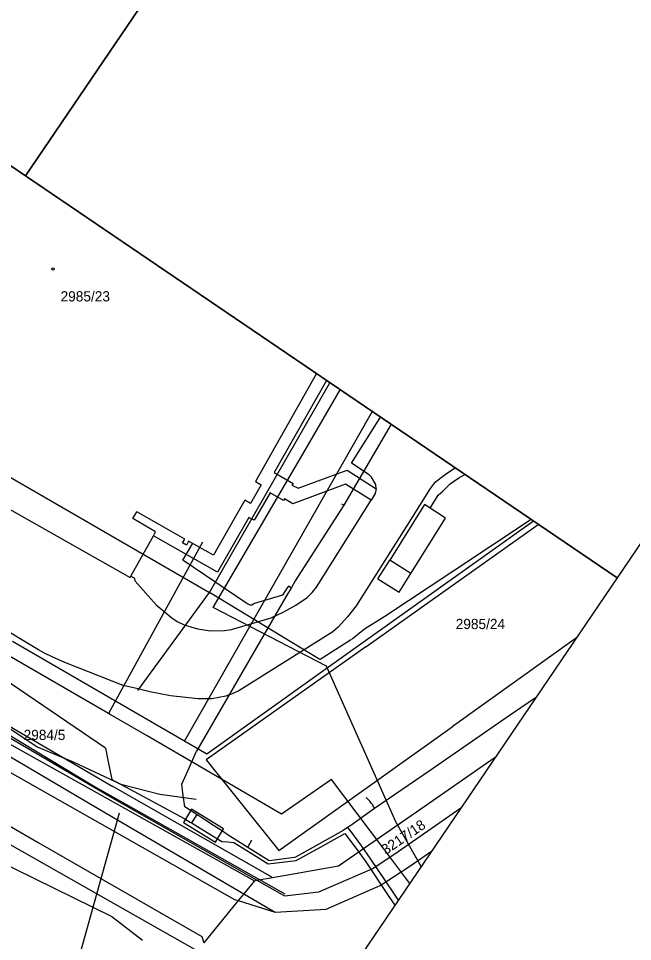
# Model space of a CAD drawing. Extents: x -620624 to -619936, y -1122925 to -1122325.
# Drawn here: x -620107.1 to -620016.9, y -1122855.2 to -1122719.7 of the extents above; entities that cross this region are included whole.
import ezdxf

# ---------------------------------------------------------------- set-up
doc = ezdxf.new("R2010")
doc.units = 0
for name, color, linetype in [('CETIN', 7, 'Continuous'), ('GasNet', 7, 'Continuous'), ('Město Bystřice-osvětlení', 7, 'Continuous'), ('RÁMY', 7, 'Continuous'), ('VAS stoka', 7, 'Continuous'), ('VAS vodovod', 7, 'Continuous'), ('Vrstva 55', 7, 'Continuous'), ('Vrstva 56', 7, 'Continuous'), ('Vrstva 57', 7, 'Continuous')]:
    doc.layers.add(name, color=color, linetype=linetype)

msp = doc.modelspace()

# ---------------------------------------------------------------- linework, layer by layer
at = {"layer": 'CETIN'}
for points in [[(-620322.39, -1122622.26), (-620301.06, -1122636.75), (-620273.54, -1122652.22), (-620253.25, -1122663.16), (-620204.02, -1122698.84), (-620159.64, -1122769.19), (-620144.67, -1122791.29), (-620140.33, -1122798.33), (-620134.98, -1122805.25), (-620121.23, -1122817.18), (-620095.95, -1122832.42), (-620068, -1122848.18)], [(-620227.04, -1122727.67), (-620227.6, -1122728.26), (-620225.24, -1122730.07), (-620192.39, -1122755.87), (-620182.03, -1122766.47), (-620178.55, -1122770.03), (-620178.11, -1122770.48), (-620148.97, -1122814.05), (-620141.74, -1122827.78), (-620093.42, -1122851.53), (-620088.91, -1122854.99)], [(-620164.26, -1122757.63), (-620162.95, -1122761.03), (-620156.11, -1122769.9), (-620136.56, -1122796.46), (-620117.89, -1122817.63), (-620104.34, -1122826.6), (-620099.09, -1122828.81), (-620092.09, -1122832.08), (-620086.33, -1122833.54), (-620081.02, -1122834.31)]]:
    msp.add_lwpolyline(points, dxfattribs=at)
at = {"layer": 'GasNet'}
for points in [[(-620049.65, -1122846.64), (-620053.62, -1122841.38), (-620061.16, -1122831.41), (-620068.48, -1122836.5), (-620088.2, -1122824.99), (-620093.66, -1122821.84), (-620093.89, -1122821.71), (-620111.26, -1122811.68), (-620133.38, -1122798.37), (-620145.72, -1122781.6), (-620162.54, -1122758.52), (-620166.3, -1122761.04), (-620166.89, -1122761.43), (-620167.47, -1122761.82), (-620169.13, -1122762.93), (-620169.19, -1122762.97)], [(-620080.07, -1122796.57), (-620093.89, -1122821.71)]]:
    msp.add_lwpolyline(points, dxfattribs=at)
at = {"layer": 'Město Bystřice-osvětlení'}
msp.add_lwpolyline([(-620092.3, -1122836.33), (-620103.44, -1122876.12), (-620128.4, -1122892.9), (-620139.78, -1122899.44)], dxfattribs=at)
at = {"layer": 'RÁMY'}
for points in [[(-620540.39, -1122447.87), (-620019.21, -1122801.81), (-620102.64, -1122924.66), (-620623.82, -1122570.71)], [(-620109.51, -1122560.98), (-620022.64, -1122619.97), (-620106.07, -1122742.82), (-620192.94, -1122683.83)], [(-620366.66, -1122565.85), (-620019.21, -1122801.81), (-620102.64, -1122924.66), (-620450.09, -1122688.7)], [(-620022.64, -1122619.97), (-619935.78, -1122678.97), (-620019.21, -1122801.81), (-620106.07, -1122742.82)]]:
    msp.add_lwpolyline(points, close=True, dxfattribs=at)
at = {"layer": 'VAS stoka'}
for p, q in [((-620079.03, -1122803.96), (-620061.38, -1122773.17)), ((-620122.37, -1122778.92), (-620079.03, -1122803.96)), ((-620089.57, -1122818.32), (-620079.03, -1122803.96)), ((-620062.84, -1122813.78), (-620079.03, -1122803.96)), ((-620061.86, -1122814.79), (-620078.5, -1122806.14)), ((-620053.33, -1122807.48), (-620056.28, -1122809.32)), ((-620056.28, -1122809.32), (-620058.12, -1122810.81)), ((-620058.19, -1122810.85), (-620062.82, -1122813.8)), ((-620047.97, -1122844.15), (-620051.68, -1122837.63))]:
    msp.add_line(p, q, dxfattribs=at)
for points in [[(-620078.5, -1122806.14), (-620064.68, -1122782.49), (-620062.36, -1122778.51), (-620059.85, -1122774.22)], [(-620031.8, -1122793.26), (-620043.05, -1122800.69), (-620053.33, -1122807.48)], [(-620051.68, -1122837.63), (-620057.91, -1122823.65), (-620061.86, -1122814.79)]]:
    msp.add_lwpolyline(points, dxfattribs=at)
at = {"layer": 'VAS vodovod'}
for p, q in [((-620055.19, -1122777.38), (-620082.75, -1122825.82)), ((-620059.31, -1122791.15), (-620059.64, -1122790.99)), ((-620080.91, -1122836.55), (-620081.7, -1122837.78))]:
    msp.add_line(p, q, dxfattribs=at)
for points in [[(-620094.32, -1122826.78), (-620136.84, -1122797.89), (-620162.06, -1122762.89), (-620162.19, -1122762.71)], [(-620052.4, -1122779.28), (-620059.31, -1122791.15), (-620066.47, -1122802.26), (-620067.02, -1122803.23), (-620067.86, -1122804.62), (-620080.94, -1122827.26)], [(-620067.05, -1122803.27), (-620067.43, -1122803.04), (-620067.65, -1122803.28), (-620068.31, -1122804.37), (-620072.43, -1122805.57), (-620072.82, -1122805.8), (-620073.06, -1122805.84), (-620073.57, -1122805.56), (-620082.95, -1122799.21), (-620081.54, -1122796.81)], [(-620031.16, -1122819.41), (-620035.32, -1122822.27), (-620046.82, -1122830.19), (-620050.81, -1122832.92), (-620054.81, -1122835.64), (-620056.56, -1122836.89), (-620058.31, -1122838.14), (-620058.56, -1122838.3), (-620058.81, -1122838.46)], [(-620094.32, -1122826.78), (-620093.93, -1122828.82), (-620093.38, -1122831.42), (-620088.09, -1122834.26), (-620082.79, -1122837.11), (-620081.87, -1122837.67), (-620081.6, -1122837.83), (-620080.01, -1122838.8), (-620077.23, -1122840.48), (-620076.35, -1122840.57), (-620075.46, -1122840.67), (-620072.96, -1122842.22), (-620070.45, -1122843.78), (-620068.4, -1122843.54), (-620066.34, -1122843.3), (-620062.75, -1122841.31), (-620059.16, -1122839.32), (-620057.68, -1122841.33), (-620056.2, -1122843.34), (-620052.72, -1122848.56), (-620051.85, -1122849.86)], [(-620076.29, -1122839.55), (-620076.85, -1122839.2), (-620078.3, -1122838.25), (-620079.76, -1122837.3), (-620080.6, -1122836.75), (-620081.33, -1122836.28), (-620082.67, -1122835.4), (-620082.9, -1122833.74), (-620083.14, -1122832.08), (-620082.04, -1122829.67), (-620080.94, -1122827.26)], [(-620054.81, -1122835.64), (-620054.88, -1122835.52), (-620054.95, -1122835.4), (-620055.02, -1122835.27), (-620055.09, -1122835.14), (-620055.19, -1122835), (-620055.29, -1122834.87), (-620055.52, -1122834.59), (-620055.75, -1122834.32), (-620056.05, -1122834.04)], [(-620058.81, -1122838.46), (-620059.44, -1122838.9), (-620063.01, -1122840.88), (-620066.44, -1122842.78), (-620066.57, -1122842.85), (-620068.43, -1122843.09), (-620070.28, -1122843.33), (-620071.85, -1122842.34), (-620073.41, -1122841.36), (-620075.13, -1122840.28), (-620076.29, -1122839.55)], [(-620058.81, -1122838.46), (-620058.6, -1122838.7), (-620058.39, -1122838.94), (-620058.35, -1122838.97), (-620056.75, -1122841.18), (-620055.49, -1122842.93), (-620052.02, -1122848.07), (-620051.33, -1122849.1)], [(-620073.41, -1122841.36), (-620073.27, -1122841.11), (-620073.12, -1122840.84), (-620073.12, -1122840.84), (-620072.99, -1122840.57), (-620072.86, -1122840.3)]]:
    msp.add_lwpolyline(points, dxfattribs=at)
msp.add_lwpolyline([(-620081.69, -1122835.75), (-620082.88, -1122837.72), (-620078.19, -1122840.59), (-620077, -1122838.62)], close=True, dxfattribs=at)
at = {"layer": 'Vrstva 55'}
for p, q in [((-620063.36, -1122771.83), (-620072.31, -1122787.67)), ((-620071.46, -1122788.15), (-620073.02, -1122790.9)), ((-620072.31, -1122787.67), (-620071.46, -1122788.15)), ((-620073.87, -1122790.42), (-620077.82, -1122797.38)), ((-620073.02, -1122790.9), (-620073.87, -1122790.42)), ((-620086.43, -1122793.99), (-620089.73, -1122792.12)), ((-620082.68, -1122796.11), (-620086.43, -1122793.99)), ((-620031.49, -1122793.48), (-620062.93, -1122815.9)), ((-620056.1, -1122811.95), (-620030.77, -1122793.96)), ((-620090.59, -1122801.55), (-620087.3, -1122795.66)), ((-620087.3, -1122795.66), (-620086.96, -1122795.04)), ((-620083.01, -1122796.68), (-620082.68, -1122796.11)), ((-620082.45, -1122797), (-620083.01, -1122796.68)), ((-620082.12, -1122796.42), (-620082.45, -1122797)), ((-620078.46, -1122798.5), (-620082.12, -1122796.42)), ((-620077.82, -1122797.38), (-620078.46, -1122798.5)), ((-620025.17, -1122810.59), (-620043.43, -1122823.66)), ((-620079.47, -1122827.69), (-620107.97, -1122811.15)), ((-620062.93, -1122815.9), (-620079.47, -1122827.69)), ((-620119.48, -1122820.03), (-620072.47, -1122846.25)), ((-620114.36, -1122820.1), (-620093.24, -1122832.45)), ((-620116.57, -1122823.25), (-620095.17, -1122835.78)), ((-620080.86, -1122856.55), (-620132.47, -1122827.27)), ((-620038.5, -1122829.12), (-620037.09, -1122828.14)), ((-620047.37, -1122835.25), (-620038.5, -1122829.12)), ((-620069.79, -1122845.77), (-620093.24, -1122832.45)), ((-620095.17, -1122835.78), (-620074.02, -1122848.16)), ((-620060.13, -1122844.05), (-620047.37, -1122835.25)), ((-620049.77, -1122844.23), (-620046.45, -1122841.92)), ((-620068.97, -1122845.62), (-620060.13, -1122844.05)), ((-620053.99, -1122846.97), (-620049.77, -1122844.23)), ((-620072.09, -1122846.18), (-620069.79, -1122845.77)), ((-620069.79, -1122845.77), (-620068.97, -1122845.62)), ((-620072.47, -1122846.25), (-620074.02, -1122848.16)), ((-620072.47, -1122846.25), (-620072.09, -1122846.18)), ((-620061.9, -1122850.43), (-620053.99, -1122846.97)), ((-620074.02, -1122848.16), (-620074.83, -1122849.15)), ((-620074.02, -1122848.16), (-620069.41, -1122850.86)), ((-620074.83, -1122849.15), (-620079.9, -1122855.37)), ((-620069.41, -1122850.86), (-620061.9, -1122850.43))]:
    msp.add_line(p, q, dxfattribs=at)
for points in [[(-620122.58, -1122783.75), (-620090.7, -1122801.75), (-620090.59, -1122801.55)], [(-620086.96, -1122795.04), (-620090.3, -1122793.12), (-620089.73, -1122792.12)], [(-620056.1, -1122811.95), (-620079.53, -1122828.52), (-620068.86, -1122841.8), (-620043.43, -1122823.66)]]:
    msp.add_lwpolyline(points, dxfattribs=at)
at = {"layer": 'Vrstva 56'}
for p, q in [((-620061.88, -1122772.83), (-620069.55, -1122786.35)), ((-620058.21, -1122785), (-620053.96, -1122778.22)), ((-620066.03, -1122788.67), (-620058.85, -1122786.02)), ((-620058.85, -1122786.02), (-620054.57, -1122788.73)), ((-620055.6, -1122786.71), (-620058.21, -1122785)), ((-620042.95, -1122785.69), (-620044.47, -1122786.69)), ((-620069.55, -1122786.35), (-620066.78, -1122787.99)), ((-620055.26, -1122787.03), (-620055.6, -1122786.71)), ((-620054.65, -1122788.11), (-620055.26, -1122787.03)), ((-620044.47, -1122786.69), (-620046.04, -1122787.93)), ((-620043.69, -1122788), (-620042.42, -1122787.14)), ((-620042.42, -1122787.14), (-620041.98, -1122786.91)), ((-620041.98, -1122786.91), (-620041.52, -1122786.66)), ((-620066.78, -1122787.99), (-620066.95, -1122788.23)), ((-620066.95, -1122788.23), (-620066.03, -1122788.67)), ((-620059.07, -1122788.06), (-620066.82, -1122790.95)), ((-620055.29, -1122790.43), (-620059.07, -1122788.06)), ((-620054.57, -1122788.73), (-620054.73, -1122789.43)), ((-620054.57, -1122788.73), (-620054.65, -1122788.11)), ((-620046.66, -1122788.71), (-620050.01, -1122794.09)), ((-620046.04, -1122787.93), (-620046.66, -1122788.71)), ((-620044.78, -1122789.08), (-620043.69, -1122788)), ((-620070.13, -1122789.33), (-620072.48, -1122793.37)), ((-620068.2, -1122790.46), (-620070.13, -1122789.33)), ((-620068.05, -1122790.2), (-620068.2, -1122790.46)), ((-620066.82, -1122790.95), (-620068.05, -1122790.2)), ((-620054.73, -1122789.43), (-620055.29, -1122790.43)), ((-620046.67, -1122791.59), (-620045.49, -1122789.69)), ((-620045.49, -1122789.69), (-620044.78, -1122789.08)), ((-620063.35, -1122803.17), (-620055.29, -1122790.43)), ((-620044.39, -1122793.03), (-620046.67, -1122791.59)), ((-620073.28, -1122792.94), (-620077.88, -1122800.99)), ((-620072.48, -1122793.37), (-620073.28, -1122792.94)), ((-620049.47, -1122801.15), (-620044.39, -1122793.03)), ((-620050.01, -1122794.09), (-620057.54, -1122805.91)), ((-620077.88, -1122800.99), (-620087.3, -1122795.66)), ((-620054.32, -1122801.97), (-620052.58, -1122799.22)), ((-620049.47, -1122801.15), (-620052.58, -1122799.22)), ((-620104.17, -1122812.35), (-620119.93, -1122803.03)), ((-620064, -1122803.96), (-620063.35, -1122803.17)), ((-620066.39, -1122805.81), (-620064.71, -1122804.67)), ((-620064.71, -1122804.67), (-620064, -1122803.96)), ((-620086.89, -1122805.77), (-620084.53, -1122807.72)), ((-620068.14, -1122806.82), (-620066.39, -1122805.81)), ((-620057.54, -1122805.91), (-620058.79, -1122807.53)), ((-620084.53, -1122807.72), (-620083.69, -1122808.26)), ((-620075.82, -1122809.38), (-620069.99, -1122807.67)), ((-620069.99, -1122807.67), (-620068.14, -1122806.82)), ((-620058.79, -1122807.53), (-620060.14, -1122809.05)), ((-620083.69, -1122808.26), (-620082.76, -1122808.7)), ((-620082.76, -1122808.7), (-620080.83, -1122809.28)), ((-620080.83, -1122809.28), (-620078.84, -1122809.59)), ((-620060.14, -1122809.05), (-620060.93, -1122809.75)), ((-620078.84, -1122809.59), (-620076.83, -1122809.56)), ((-620076.83, -1122809.56), (-620075.82, -1122809.38)), ((-620060.93, -1122809.75), (-620074.77, -1122818.38)), ((-620103.27, -1122812.85), (-620104.17, -1122812.35)), ((-620102.16, -1122813.38), (-620103.27, -1122812.85)), ((-620100.32, -1122814.22), (-620102.16, -1122813.38)), ((-620098.43, -1122814.97), (-620100.32, -1122814.22)), ((-620091.75, -1122817.59), (-620098.43, -1122814.97)), ((-620089.79, -1122818.03), (-620091.75, -1122817.59)), ((-620087.81, -1122818.54), (-620089.79, -1122818.03)), ((-620084.78, -1122819.14), (-620087.81, -1122818.54)), ((-620074.77, -1122818.38), (-620075.71, -1122818.84)), ((-620127.92, -1122819.29), (-620075.39, -1122849.03)), ((-620080.74, -1122819.56), (-620084.78, -1122819.14)), ((-620078.69, -1122819.55), (-620080.74, -1122819.56)), ((-620076.68, -1122819.17), (-620078.69, -1122819.55)), ((-620075.71, -1122818.84), (-620076.68, -1122819.17)), ((-620093.98, -1122833.75), (-620115.22, -1122821.33)), ((-620129.64, -1122825.94), (-620104.21, -1122840.64)), ((-620072.09, -1122846.18), (-620093.98, -1122833.75)), ((-620051.34, -1122841.97), (-620042.13, -1122835.56)), ((-620104.21, -1122840.64), (-620080.18, -1122854.43)), ((-620055.09, -1122844.45), (-620051.34, -1122841.97)), ((-620063, -1122847.91), (-620055.09, -1122844.45)), ((-620072.09, -1122846.18), (-620068.02, -1122848.49)), ((-620068.02, -1122848.49), (-620063, -1122847.91)), ((-620075.39, -1122849.03), (-620074.83, -1122849.15)), ((-620074.83, -1122849.15), (-620069.41, -1122850.86)), ((-620080.18, -1122854.43), (-620079.9, -1122855.37))]:
    msp.add_line(p, q, dxfattribs=at)
for points in [[(-620046.67, -1122791.59), (-620047.49, -1122791.07), (-620052.58, -1122799.22)], [(-620054.32, -1122801.97), (-620051.2, -1122803.92), (-620049.47, -1122801.15)], [(-620090.59, -1122801.55), (-620090.11, -1122801.83), (-620089.99, -1122802.28), (-620086.89, -1122805.77)]]:
    msp.add_lwpolyline(points, dxfattribs=at)
at = {"layer": 'Vrstva 57'}
msp.add_circle((-620102.03, -1122756.47), 0.175, dxfattribs=at)

# ---------------------------------------------------------------- texts
for s, p in [('2985/23', (-620100.92, -1122761.25)), ('2985/24', (-620042.9, -1122809.33)), ('2984/5', (-620106.35, -1122825.61))]:
    msp.add_text(s, height=1.5, dxfattribs=at).set_placement(p)
msp.add_text('3217/18', height=1.5, rotation=34.2, dxfattribs=at).set_placement((-620053.16, -1122842.5))

doc.saveas('drawing.dxf')
